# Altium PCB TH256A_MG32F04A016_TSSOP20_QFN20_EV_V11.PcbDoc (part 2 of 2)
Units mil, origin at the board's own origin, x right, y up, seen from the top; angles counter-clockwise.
Board outline 4094.49 x 2637.8 mil, 2 copper layers (Top Layer, Bottom Layer); 134 components, 99 nets, 551 pads, 259 vias.
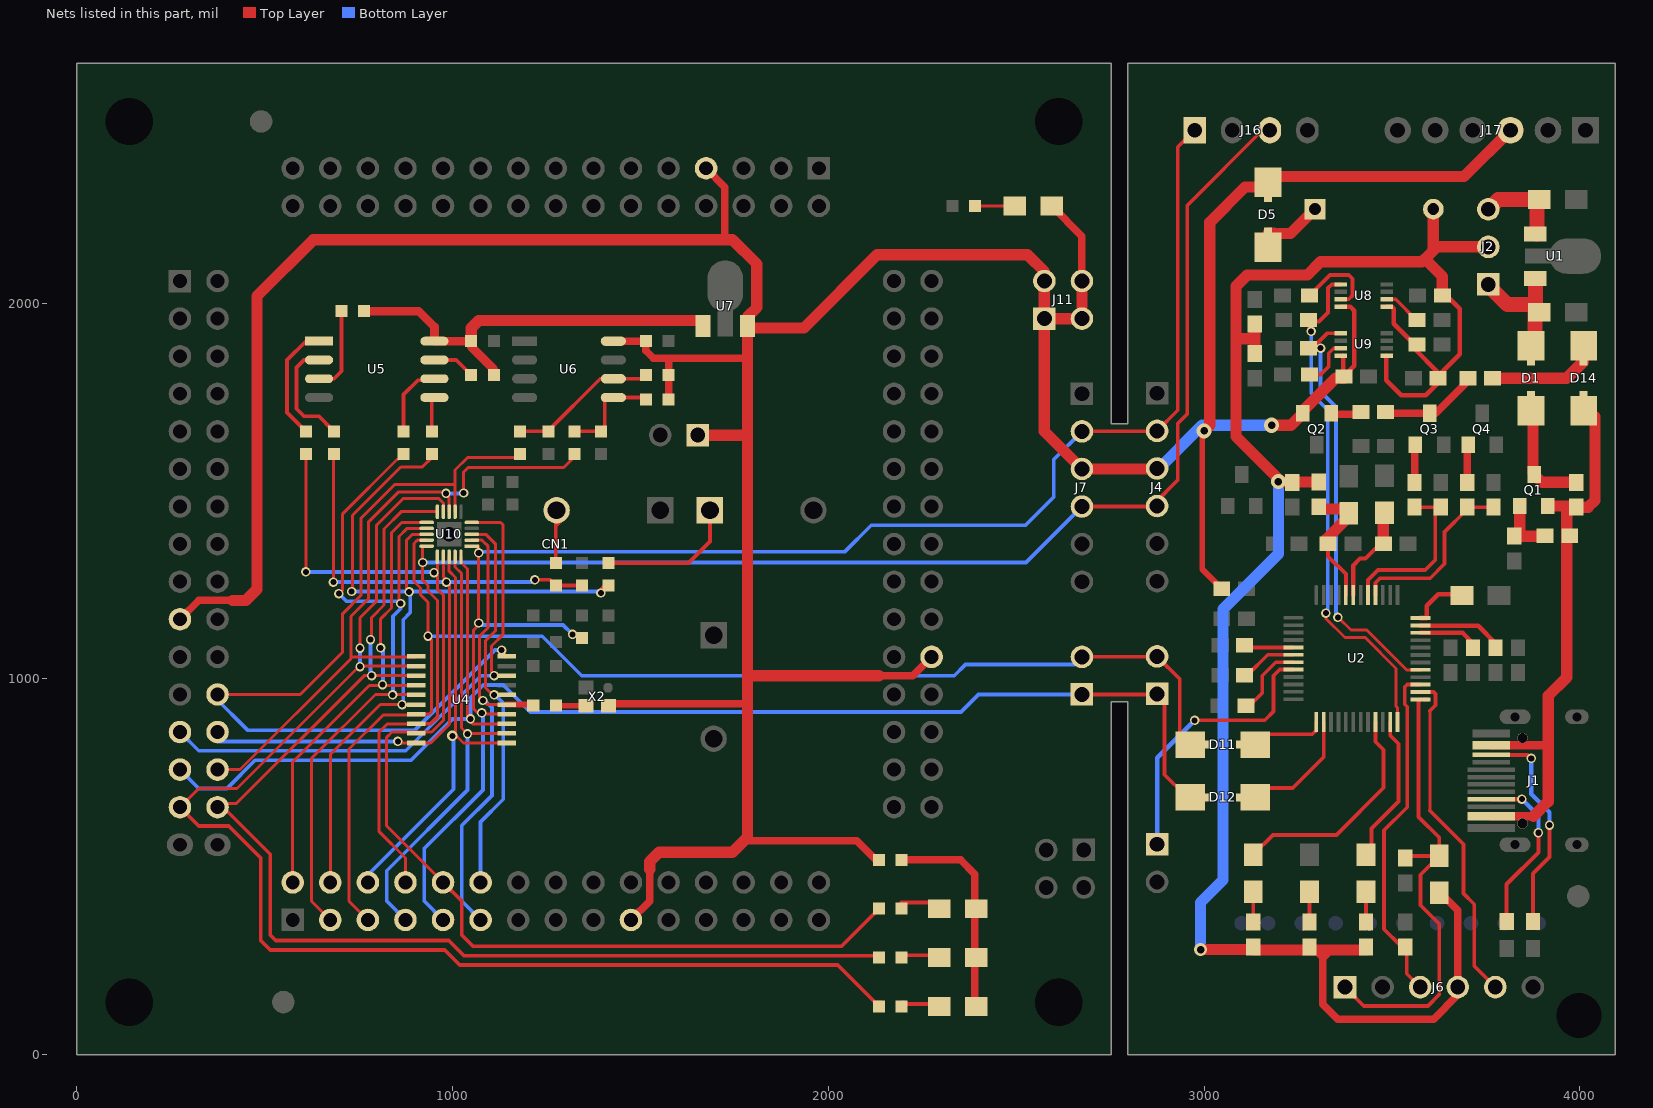
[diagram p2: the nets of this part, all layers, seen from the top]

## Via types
v1: diameter 20, hole 12, Top Layer to Bottom Layer, tented both sides, 173 vias
v2: diameter 25, hole 16, Top Layer to Bottom Layer, tented both sides, 58 vias
v3: diameter 30, hole 12, Top Layer to Bottom Layer, tented both sides, 13 vias
v4: diameter 25, hole 12, Top Layer to Bottom Layer, tented both sides, 6 vias
v5: diameter 40, hole 20, Top Layer to Bottom Layer, tented both sides, 3 vias
v6: diameter 28, hole 16, Top Layer to Bottom Layer, tented both sides, 2 vias
v7: diameter 30, hole 16, Top Layer to Bottom Layer, tented both sides, 2 vias
v8: diameter 35, hole 20, Top Layer to Bottom Layer, tented both sides, 1 vias
v9: diameter 15, hole 12, Top Layer to Bottom Layer, tented both sides, 1 vias

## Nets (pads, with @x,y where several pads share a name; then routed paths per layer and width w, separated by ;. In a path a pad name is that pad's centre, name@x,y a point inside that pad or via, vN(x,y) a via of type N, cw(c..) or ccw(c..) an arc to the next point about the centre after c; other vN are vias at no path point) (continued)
MLINK_RXD: CN1.5 D11.2 J5.2 J8.2 U4.17 U10.14 | length 3570.1
  Top Layer w8: CN1.5@775.04,358.74 725.04,408.74 725.04,813.74 815.04,903.74 903.88,903.74 922.44,903.74 U4.17@925.04,906.34 ; U4.17@903.88,906.34 U4.17@925.04,906.34 ; U10.14@931.41,1369.21 906.51,1369.21 897.72,1360.42 897.72,1259.06 915.04,1241.74 915.04,1223.74 935.04,1203.74 v2(935.04,1113.74) 944.04,1104.74 944.04,1093.74 ; 944.04,1063.74 944.04,1093.74 ; U4.17@925.04,906.34 937.64,906.34 944.04,912.74 944.04,1093.74
  Top Layer w10: J8.2@2675.04,1058.74 J5.2@2875.04,1058.74 ; J5.2@2875.04,1060 2935.04,1000 2935.04,825 D11.2@2935.04,810
  Bottom Layer w10: v2(935.04,1113.74) 1239.04,1113.74 1344.04,1008.74 2335.04,1008.74 2365.04,1038.74 2655.04,1038.74 J8.2@2675.04,1058.74
MLINK_TXD: CN1.117 D12.1 J5.1 J8.1 U4.3 U10.20 | length 3656.5
  Top Layer w8: U10.20@1022.91,1324.96 1022.91,1309.87 1040.04,1292.74 1040.04,894.74 1044.54,890.24 1054.04,880.74 U4.3@1144.04,880.74 ; J5.1@2875.04,960 J5.1@2880.81,954.23
  Top Layer w10: J8.1@2675.04,958.74 J5.1@2875.04,958.74 ; J5.1@2895.04,958 2895.04,745 D12.1@2948.43,691.61
  Bottom Layer w10: CN1.117@275.04,758.74 325.04,708.74 400.11,708.74 475.04,783.67 889.97,783.67 1000.04,893.74 v2@1044.04,893.74 ; v2(1048.04,893.74) 1048.04,949.74 1082.04,983.74 1135.04,983.74 1207.04,911.74 2353.04,911.74 2400.04,958.74 J8.1@2675.04,958.74
NetC2_2: C2.2 Q1.1 R5.2 | length 165
  Top Layer w30: R5.2@3825.04,1380 R5.2@3840.04,1380 ; Q1.1@3840.04,1460 R5.2@3840.04,1380 ; C2.2@3910.04,1380 3907,1380 R5.2@3840.04,1380
NetC6_1: C6.1 C7.2 R10.2 U2.44 | length 332.7
  Top Layer w11: C7.2@3330,1360 3330,1326 3377.23,1278.77 U2.44@3377.23,1223.13
  Top Layer w30: R10.2@3320.04,1452 3385,1452 C6.1@3385,1440.79 3385,1432 3324,1371 C7.2@3324,1366
NetC8_2: C8.2 C9.1 U2.43 | length 251
  Top Layer w11: U2.43@3396.92,1223.13 3396.92,1301.92 3415,1320 3429,1320 3465.5,1356.5 3477,1356.5 C8.2@3480.5,1356.5
  Top Layer w30: C8.2@3477,1360 C9.1@3477,1426.05
NetC11_1: C11.1 U2.36 | length 149.7
  Top Layer w12: U2.36@3575.5,1162.16 3592.2,1162.16 3592.2,1194.68 3622.9,1225.39 C11.1@3679.94,1225.39
NetD1_1: D1.1 Q1.3 R1.2 | length 276.4
  Top Layer w30: D1.1@3875,1698.39 3875,1546.98 Q1.3@3878.04,1543.94 3898.98,1523 R1.2@3990.04,1523
NetD2_1: D2.1 R6.2 | length 80.8
  Top Layer w10: R6.2@3130.59,353.26 D2.1@3130.59,434.05
NetD3_1: D3.1 R9.2 | length 80.8
  Top Layer w10: R9.2@3430.59,353.26 D3.1@3430.59,434.05
NetD4_1: D4.1 R11.2 | length 80.8
  Top Layer w10: R11.2@3280.59,353.26 D4.1@3280.59,434.05
NetD5_1: D5.1 SW1.1 | length 154.2
  Top Layer w30: D5.1@3170,2185.93 3185.93,2185.93 3185,2185 3230.04,2185 SW1.1@3295.04,2250
NetD8_1: D8.1 D9.1 D10.1 R58.1 | length 550.6
  Top Layer w20: R58.1@2195.04,518.74 2351.9,518.74 2390,480.64 2390,388.74 2390,258.74 D10.1@2390,140.79
NetD8_2: D8.2 R54.2 | length 95.8
  Top Layer w10: 2195.04,405 D8.2@2290.79,405
NetD9_2: D9.2 R55.2 | length 95.8
  Top Layer w10: R55.2@2189.94,265 2195.04,265 D9.2@2285.73,265
NetD10_2: D10.2 R56.2 | length 95.8
  Top Layer w10: R56.2@2196.58,140 R56.2@2200,140 ; R56.2@2199.94,135 D10.2@2292.3,135
NetD11_1: D11.1 U2.13 | length 188.6
  Top Layer w10: D11.1@3136.65,852.74 3288.04,852.74 3298.49,863.19 U2.13@3298.49,885.65
NetD12_2: D12.2 U2.14 | length 296
  Top Layer w10: D12.2@3150.04,709.74 3236.14,709.74 3318.18,791.78 U2.14@3318.18,885.65
NetD13_2: D13.2 R43.2 | length 105.8
  Top Layer w8: R43.2@2390.04,2258.74 D13.2@2495.83,2258.74
NetD14_2: D14.2 R17.1 | length 272.5
  Top Layer w30: R17.1@3768,1800 3965,1800 D14.2@4009.08,1844.07 ; D14.2@3998.15,1868.15 D14.2@4010,1868.15 ; D14.2@4004.08,1844.07 D14.2@4005,1845
NetJ1_A5: J1.A5 R26.1 | length 460.3
  Top Layer w11: J1.A5@3763.84,679.9 v2(3845.59,679.9) ; R26.1@3805.04,354.74 3805.04,453.74 3890.04,538.74 v2@3890.04,590.74
  Bottom Layer w11: v2(3845.59,679.9) 3889.59,635.9 v2(3889.59,590.74)
NetJ1_B5: J1.B5 R27.2 | length 582.9
  Top Layer w11: J1.B5@3763.84,798.01 3861.32,798.01 v2(3870.59,788.74) ; R27.2@3875.04,354.74 3875.04,481.74 3919.04,525.74 v2(3919.04,610.74)
  Bottom Layer w11: v2(3870.59,788.74) 3870.59,693.74 3919.04,645.29 v2(3919.04,610.74)
NetQ2_1: Q2.1 R18.2 | length 72
  Top Layer w20: Q2.1@3338,1703.94 R18.2@3410,1703.94
NetQ3_1: Q3.1 R19.2 | length 97.5
  Top Layer w20: R19.2@3560.04,1523 Q3.1@3560.04,1620.53
NetQ3_2: Q3.2 R17.2 R18.1 | length 242.2
  Top Layer w20: R18.1@3503.03,1706.97 Q3.2@3600.54,1706.97 3616.97,1706.97 3702,1792 R17.2@3702,1800
NetQ4_1: Q4.1 R23.2 | length 97.5
  Top Layer w20: R23.2@3700.04,1523 Q4.1@3700.04,1620.53
NetR15_1: R15.1 U2.35 | length 263.6
  Top Layer w12: U2.35@3575.5,1141.47 3605.04,1141.47 ; 3637.3,1141.47 3605.04,1141.47 ; R15.1@3775.59,1083 3775.59,1095 3729.12,1141.47 3605.04,1141.47
NetR16_1: R16.1 U2.34 | length 163.6
  Top Layer w12: U2.34@3575.5,1122.79 3687.8,1122.79 3715.59,1095 R16.1@3715.59,1083
NetR29_2: R29.2 U8.7 | length 202.9
  Top Layer w10: R29.2@3295,2035 3335,2075 3385,2075 3395,2065 3395,2020 3385.16,2010.16 U8.7@3363.98,2010.16 U8.7@3361.86,2010.16
NetR30_2: R30.2 U9.7 | length 132.5
  Top Layer w10: R30.2@3281,1810 3310,1810 3331.5,1831.5 3331.5,1866.5 3345.16,1880.16 U9.7@3363.98,1880.16
NetR59_1: R59.1 U5.7 | length 114.5
  Top Layer w10: U5.7@952.13,1848.74 1010.04,1848.74 R59.1@1050.04,1808.74
NetR60_2: R60.2 U5.3 | length 218.2
  Top Layer w10: U5.3@645.04,1798.74 684.91,1798.74 705.04,1818.87 R60.2@705.04,1968.74
NetR64_2: R64.2 U8.2 | length 108.2
  Top Layer w10: U8.2@3486.02,2010.16 3509.84,2010.16 R64.2@3566,1954 ; R64.2@3553.5,1968.5 R64.2@3557,1965
NetR70_1: R70.1 SW4.2 | length 169.2
  Top Layer w10: R70.1@1275.04,1308.74 1275.04,1406.54 ; SW4.2@1275.04,1446.54 1275.04,1406.54 ; SW4.2@1297.24,1428.74 1275.04,1406.54
NetR72_2: R72.2 SW3.1 | length 376.6
  Top Layer w10: R72.2@1415.04,1308.74 1628.04,1308.74 1685.04,1365.74 SW3.1@1685.04,1448.74
P44: J6.5 U2.26 | length 900.8
  Top Layer w8: 3600.59,650 3600.59,915
  Top Layer w10: U2.26@3575.5,965.31 3610.28,965.31 3615.59,960 3615.59,930 3600.59,915 ; 3600.59,650 3690.59,560 3690.59,429 3719.14,400.45 3719.14,235.9 J6.5@3775.04,180
P45: J6.3 R25.1 U2.27 | length 931.6
  Top Layer w10: R25.1@3539.32,290.72 3539.32,287 3539.32,215.72 J6.3@3575.04,180 ; R25.1@3540.59,292 3535.59,292 3521.03,292 3479.04,333.99 3479.04,597.19 3540.59,658.74 3540.59,926 3534,932.59 3534,978.41 3540.58,984.99 U2.27@3575.5,984.99 ; J6.3@3576.32,181.28 J6.3@3583.59,174
PA0: CN1.114 R61.1 U4.10 U10.7 | length 2264.6
  Top Layer w8: CN1.114@375.04,958.74 595.04,958.74 708.04,1071.74 708.04,1173.74 757.35,1223.05 757.35,1428.51 845.61,1516.77 1007.16,1516.77 ; U10.7@1007.16,1444.96 1007.16,1516.77 ; U4.10@1135.92,1059.23 U4.10@1138.04,1059.23 ; U4.10@1138.04,1058.94 U4.10@1138.04,1059.23 ; v2@1138.04,1075.74 1138.04,1059.94 U4.10@1138.04,1059.23 ; U4.10@1144.04,1059.94 1143.33,1059.23 U4.10@1138.04,1059.23 ; R61.1@1180.04,1588.74 1040.04,1588.74 1007.16,1555.86 1007.16,1516.77
  Bottom Layer w10: CN1.114@360.04,958.74 367.54,951.24 455.04,863.74 900.04,863.74 1113.04,1076.74 v2(1131.04,1076.74)
PA0_I2C1_SCL: C46.1 R61.2 R68.2 U6.6 | length 381.4
  Top Layer w10: R61.2@1180.04,1658.74 1253.41,1658.74 1254.22,1659.56 1393.41,1798.74 U6.6@1428.15,1798.74 R68.2@1503.41,1798.74
PA1: CN1.115 U4.8 U10.5 | length 1428.8
  Top Layer w8: U10.5@1051.41,1416.46 1128.39,1416.46 1135.04,1409.8 1135.04,1118.74 1104.04,1087.74 1104.04,1019.74
  Bottom Layer w10: CN1.115@275.04,858.74 325.04,808.74 876.04,808.74 1076.04,1008.74 v2(1111.04,1008.74)
PA2: CN1.116 R52.1 R70.2 R71.1 U4.20 U10.17 | length 2073.4
  Top Layer w8: v2@684.04,1261.74 R52.1@684.04,1598.74 ; v2@864.24,829.54 U4.20@903.88,829.54 942.04,829.54 992.04,879.54 v2@992.04,1255.74 ; U10.17@975.67,1324.96 975.67,1272.11 v2@987.04,1260.74
  Top Layer w10: v2(1219.45,1263.74) 1260.04,1263.74 R70.2@1275.04,1248.74 R71.1@1345.04,1248.74
  Bottom Layer w10: CN1.116@375.04,833.74 v2(855.04,833.74) v2@860.04,833.74 ; v2(683.04,1257.74) v2(984.04,1257.74) v2@1209.04,1257.74
PA2_SPI_MISO: R52.2 U5.2 | length 296
  Top Layer w10: U5.2@645.04,1848.74 605.04,1848.74 585.04,1828.74 585.04,1718.74 605.04,1698.74 644.94,1698.74 R52.2@679.94,1663.74
PA4: CN1.118 R51.1 U4.11 U10.8 | length 1739.4
  Top Layer w8: CN1.118@375.04,758.74 435.04,758.74 730.04,1053.74 730.04,1057.74 ; U4.11@903.88,1059.94 901.68,1057.74 730.04,1057.74 ; U10.8@991.41,1444.96 991.41,1482.37 981.54,1492.24 977.01,1496.77 855.61,1496.77 777.35,1418.51 777.35,1214.05 730.04,1166.74 730.04,1057.74 ; v2(1030.04,1494.74) 1030.04,1550.74 1042.04,1562.74 1296.04,1562.74 R51.1@1324.54,1591.24
  Bottom Layer w10: v2(983.04,1493.74) v2@1029.04,1493.74
PA4_I2C1_SDA: C45.1 R51.2 R57.2 U6.5 | length 245.9
  Top Layer w10: R51.2@1325.04,1658.74 C45.1@1395.04,1658.74 ; C45.1@1405.04,1658.74 1405.04,1748.74 U6.5@1405.04,1752.74 ; U6.5@1428.15,1748.74 R57.2@1510.04,1748.74
PA5: CN1.119 R56.1 U4.12 U10.9 | length 3625.2
  Top Layer w8: CN1.119@275.04,658.74 325.04,708.74 427.04,708.74 748.54,1030.24 748.54,1032.74 748.54,1035.24 v2@749.04,1035.74 ; v2@749.04,1034.34 754.04,1034.34 U4.12@903.88,1034.34 ; v2@749.04,1081.74 751.54,1084.24 754.04,1086.74 754.04,1162.74 797.97,1206.67 797.97,1409.14 868.52,1479.69 964.09,1479.69 975.67,1468.11 U10.9@975.67,1444.96
  Top Layer w10: CN1.119@275.04,658.74 325.04,608.74 405.04,608.74 490.04,523.74 490.04,303.74 515.04,278.74 979.68,278.74 1019.68,238.74 2025.04,238.74 2123.78,140 2135.04,140 R56.1@2140,140
  Bottom Layer w10: v2@754.04,1035.74 v2(754.04,1081.74)
  other v2: 754.04,1032.74
PA6: CN1.120 R55.1 U4.13 U10.10 | length 3259.2
  Top Layer w8: CN1.120@375.04,658.74 390.04,658.74 400.04,668.74 425.04,668.74 765.04,1008.74 v2(785.04,1008.74) U4.13@903.88,1008.74 ; v2@785.04,1104.74 785.04,1163.74 817.97,1196.67 817.97,1399.14 863.8,1444.96 U10.10@959.92,1444.96
  Top Layer w10: CN1.120@390.04,658.74 515.04,533.74 515.04,318.74 530.04,303.74 990.04,303.74 1030.04,263.74 2118.74,263.74
  Bottom Layer w10: v2@782.04,1008.74 v2(782.04,1104.74) ; v2@783.54,1106.24 v2@785.04,1104.74
PA7: CN1.2 U4.14 U10.11 | length 1287.9
  Top Layer w8: CN1.2@575.04,458.74 575.04,508.74 ; 575.04,538.74 575.04,508.74 ; v2(809.04,1082.74) 809.04,1159.81 837.97,1188.74 837.97,1389.14 865.29,1416.46 U10.11@931.41,1416.46 ; U4.14@903.88,983.14 814.04,983.14 813.95,983.14 813.2,983.9 811.2,985.9 808.04,982.74 779.04,982.74 575.04,778.74 575.04,508.74
  Bottom Layer w10: v2@815.04,983.74 815.04,984.74 v2@815.04,1082.74
  other v2: 814.04,984.74
PA8: CN1.3 R65.1 U4.15 U10.12 | length 1929.2
  Top Layer w8: CN1.3@675.04,358.74 625.04,408.74 625.04,788.74 795.04,958.74 841.04,958.74 903.88,958.74 U4.15@905.04,958.74 ; v2(698.04,1226.74) 708.04,1236.74 708.04,1439.2 852.58,1583.74 855.04,1583.74 R65.1@870.04,1598.74 ; v2@857.97,1205.74 857.97,1379.14 879.54,1400.71 U10.12@931.41,1400.71
  Bottom Layer w10: v2(698.04,1226.74) 718.04,1206.74 v2@862.04,1206.74 ; v2@842.04,958.74 842.04,1166.74 862.04,1186.74 v2(862.04,1200.74) v2@862.04,1205.74
  other v2: 841.04,957.74
PA8_SPI_SCK: R65.2 U5.6 | length 217.2
  Top Layer w10: R65.2@870.04,1658.74 870.04,1756.52 908.52,1795 952.13,1795 U5.6@973.54,1795
PA9: CN1.4 R53.1 R72.1 U4.16 U10.13 | length 2287.5
  Top Layer w8: CN1.4@675.04,458.74 675.04,798.74 808.24,931.94 866.04,931.94 U4.16@903.88,931.94 ; v2@734.35,1232.74 734.35,1435.51 862.58,1563.74 920.04,1563.74 945.04,1588.74 R53.1@945.04,1598.74 ; v2@877.35,1240.43 877.35,1368.51 893.8,1384.96 U10.13@931.41,1384.96
  Top Layer w10: v2(1395.04,1228.74) 1395.04,1238.74 R72.1@1410.04,1253.74
  Bottom Layer w10: v2@734.35,1232.74 885.04,1232.74 v2@1395.04,1232.74 ; v2@869.04,940.94 869.04,1157.74 888.04,1176.74 v2@888.04,1228.74
  other v2: 866.04,931.74 885.04,1231.74 732.04,1232.74
PA9_SPI_MOSI: R53.2 U5.5 | length 90
  Top Layer w10: R53.2@945.04,1658.74 U5.5@945.04,1748.74
PA11: CN1.6 U4.1 U10.18 | length 1107.6
  Top Layer w8: U10.18@991.41,1324.96 991.41,1286.37 1008.04,1269.74 1008.04,850.74 1029.24,829.54 U4.1@1144.04,829.54
  Bottom Layer w10: CN1.6@775.04,458.74 775.04,478.74 1002.54,706.24 v6@1002.54,846.24
  other v6: 1000.04,848.74
PA12: CN1.7 U4.2 U10.19 | length 1193
  Top Layer w8: U10.19@1007.16,1324.96 1007.16,1297.74 1024.04,1280.86 1024.04,869.74 1038.64,855.14 1040.04,855.14 U4.2@1144.04,855.14
  Bottom Layer w10: CN1.7@875.04,358.74 825.04,408.74 825.04,489.66 1040.04,704.66 v2(1040.04,853.74)
PA13_SWDIO: CN1.8 J4.4 J7.4 J16.3 U4.18 U10.15 | length 4405.8
  Top Layer w8: CN1.8@875.04,458.74 875.04,523.74 805.04,593.74 805.04,858.74 827.04,880.74 U4.18@903.88,880.74 ; U10.15@920.04,1353.74 920.04,1353.46 920.04,1309.74 920.04,1263.74 935.04,1248.74 935.04,1233.74 960.04,1208.74 960.04,898.74
  Top Layer w10: U4.18@903.88,880.74 942.04,880.74 960.04,898.74 ; J7.4@2675.04,1458.74 J4.4@2860.04,1458.74 ; J4.4@2868.04,1467 2930.04,1529 2930.04,1680 2955.04,1705 2955.04,2260.04 3155,2460 J16.3@3175.04,2460
  Bottom Layer w10: v2@920.04,1309.74 v2(921.04,1309.74) 1680.04,1309.74 ; 1880.04,1309.74 1680.04,1309.74 ; J7.4@2675.04,1458.74 2526.04,1309.74 1680.04,1309.74
PA14_SWCLK: CN1.9 J4.2 J7.2 J16.1 R69.1 U4.4 U10.1 | length 4290.9
  Top Layer w8: U10.1@1070.04,1353.74 1070.04,1353.46 v2(1070.04,1335.74) v2(1070.04,1148.74) 1070.04,1143.74 1056.04,1129.74 1056.04,920.74 v2@1070.44,906.34 ; v2@1078.04,906.34 U4.4@1144.04,906.34
  Top Layer w10: v2@1315.04,1113.74 1319.45,1113.74 R69.1@1345.04,1113.74 ; J7.2@2675.04,1658.74 J4.2@2875.04,1658.74 ; J4.2@2875.04,1660 2930.04,1715 2930.04,2415 J16.1@2975.04,2460
  Bottom Layer w10: CN1.9@975.04,358.74 925.04,408.74 925.04,548.74 1081.04,704.74 v2@1081.04,909.74 ; v2@1070.04,1143.74 1294.45,1143.74 v2(1319.45,1118.74) ; v2@1070.04,1333.74 1071.04,1334.74 1075.04,1338.74 2044.68,1338.74 2114.68,1408.74 2525.04,1408.74 2600.04,1483.74 2600.04,1583.74 J7.2@2675.04,1658.74
  other v2: 1078.04,909.74
PA15: CN1.10 R54.1 R66.1 U4.19 U10.16 | length 3029.1
  Top Layer w8: v2@610.04,1294.74 R66.1@610.04,1598.74 ; U10.16@959.92,1324.96 959.92,1282.74 959.92,1238.86 976.04,1222.74 976.04,889.94 944.84,858.74 903.88,858.74 839.04,858.74 825.04,844.74 825.04,608.74 CN1.10@975.04,458.74
  Top Layer w10: CN1.10@975.04,458.74 1025.04,408.74 1025.04,318.74 1055.04,288.74 2035.04,288.74 R54.1@2135.04,388.74
  Bottom Layer w10: v2(610.04,1284.74) v2@951.04,1284.74
  other v2: 951.04,1282.74
PA15_SPI_NSS: R66.2 U5.1 | length 316.4
  Top Layer w10: R66.2@610.04,1658.74 560.04,1708.74 560.04,1848.74 610.04,1898.74 U5.1@645.04,1898.74
PASS: D3.2 U2.23 | length 394.2
  Top Layer w10: D3.2@3445.59,530 3445.59,532.47 3445.59,602.29 3517.04,673.74 3517.04,827.74 3495.34,849.44 U2.23@3495.34,885.65
PB0: CN1.11 R67.1 U4.5 U10.2 | length 1262.9
  Top Layer w8: U10.2@1051.41,1369.21 1078.57,1369.21 1095.04,1352.74 1095.04,1136.74 1072.04,1113.74 1072.04,951.74 v2(1081.04,942.74) 1091.84,931.94 U4.5@1144.04,931.94
  Top Layer w15: U4.5@1144.04,931.94 R67.1@1215.04,931.94
  Bottom Layer w10: CN1.11@1075.04,358.74 1025.04,408.74 1025.04,609.66 1105.04,689.66 1105.04,923.74 1086.04,942.74 v2(1081.04,942.74)
PB0_OSCIN: R67.2 X2.3 | length 80
  Top Layer w15: R67.2@1275.04,928.74 X2.3@1355.04,928.74
PB1: CN1.12 U4.6 U10.3 | length 1065.9
  Top Layer w8: U10.3@1051.41,1384.96 1088.82,1384.96 1115.04,1358.74 1115.04,1128.74 1088.04,1101.74 1088.04,976.74 1107.24,957.54 v2(1111.04,957.54) U4.6@1144.04,957.54
  Bottom Layer w10: CN1.12@1075.04,458.74 1075.04,619.74 1135.04,679.74 1135.04,935.74 v2@1112.14,958.64
RST: C12.2 J6.1 R22.2 U2.25 | length 1228.1
  Top Layer w10: J6.1@3375.04,180 3425.04,130 3595.59,130 3625.59,160 3625.59,348 3575.59,398 3575.59,479.21 C12.2@3625.59,529.21 ; R22.2@3541.8,529.21 C12.2@3625.59,529.21 ; U2.25@3575.59,945 3570.59,940 3570.59,633 3625.59,578 C12.2@3625.59,529.21 ; U2.25@3585.04,945.62 U2.25@3594.42,945.62
RST_CTRL_51: R19.1 R20.1 U2.41 | length 451.6
  Top Layer w10: U2.41@3436.29,1223.13 3436.29,1263.29 3463,1290 3588.74,1290 3615.04,1316.3 R20.1@3615.04,1457 ; R19.1@3560.04,1457 R20.1@3615.04,1457 ; R20.1@3630.04,1457 R20.1@3615.04,1457
RST_CTRL_ARM: R23.1 R24.1 U2.40 | length 474.1
  Top Layer w10: U2.40@3455.97,1223.13 3455.97,1256.14 3467.84,1268 3601.74,1268 3640.04,1306.3 3640.04,1391.3 R23.1@3697.5,1448.76 ; R23.1@3700.04,1457 R24.1@3770.04,1457
SWD_SCL_DIR: R63.2 U2.29 U9.5 | length 1149.4
  Top Layer w8: v2@3356.5,1164.5 3391,1130 3433,1130 3538.64,1024.36 U2.29@3575.5,1024.36
  Top Layer w10: R63.2@3289,1869 R63.2@3295,1875 ; R63.2@3290,1883 R63.2@3290.22,1882.64 ; R63.2@3292.47,1879.04 R63.2@3290.22,1882.64 ; R63.2@3292.93,1875 R63.2@3295,1875 ; v2@3311.93,1875 3310,1875 R63.2@3295,1875 ; U9.5@3363.98,1919.53 3327.11,1919.53 3298.79,1891.21 R63.2@3290.22,1882.64
  Bottom Layer w10: v2(3310,1880) 3310,1764.49 3351,1723.49 3351,1495 ; 3351,1505 3351,1495 ; v2@3361,1160 3356.5,1164.5 3351,1170 3351,1495
  other v2: 3356,1164
SWD_SDA_DIR: R62.2 U2.24 U8.5 | length 1381.2
  Top Layer w8: v2(3324,1175) 3324,1161 3375,1110 3429,1110 3511,1028 3511,927 3515.03,922.97 U2.24@3515.03,885.65
  Top Layer w10: v2@3280,1925 R62.2@3280,1951 ; R62.2@3282,1951 R62.2@3285,1951 ; R62.2@3285,1957 3285,1955 R62.2@3285,1951 ; U8.5@3363.98,2049.53 3339.53,2049.53 3330,2040 3330,1975 3306,1951 R62.2@3285,1951
  Bottom Layer w10: v2(3285,1925) 3285,1760 3329,1716 3329,1485 ; v2@3329,1175 3329,1485 ; 3329,1505 3329,1485
TOOL_OPTION0: R2.1 U2.5 | length 121.1
  Top Layer w10: R2.1@3118.04,1080 3121.96,1083.92 U2.5@3237.52,1083.92
TOOL_OPTION1: R3.1 U2.6 | length 142.8
  Top Layer w10: R3.1@3116.54,1011.54 3169.23,1064.23 U2.6@3237.52,1064.23
TOOL_OPTION2: R28.1 U2.7 | length 191.4
  Top Layer w10: R28.1@3121.04,928.74 3155.04,962.74 3155.04,1008.74 3190.85,1044.55 U2.7@3237.52,1044.55
USBOK: D2.2 U2.21 | length 605
  Top Layer w10: D2.2@3130.59,532.47 3183.12,585 3352.3,585 3477.67,710.37 3477.67,811.43 3455.97,833.13 U2.21@3455.97,885.65
VCC3: C47.1 R59.2 R60.1 U5.8 U7.1 | length 1115.4
  Top Layer w23: R60.1@765.04,1978.74 910.04,1978.74 952.13,1936.65 U5.8@952.13,1898.74 C47.1@1050.04,1898.74 1050.04,1883.74 1110.04,1823.74 R59.2@1110.04,1808.74
  Top Layer w30: C47.1@1050.04,1898.74 1050.04,1933.74 1070.04,1953.74 U7.1@1666.93,1953.74
VCC_USB: C2.1 D14.1 J1.A4 J1.A9 J1.M5 J1.M6 Q1.2 R1.1 | length 1456.2
  Top Layer w22: J1.A4@3763.84,634.61 3847.24,634.61 3876.67,634.61 ; J1.A9@3763.84,823.62 3847.24,823.62 3915.59,823.62
  Top Layer w30: 3876.67,634.61 3915.59,673.54 3915.59,823.62 3915.59,955 3964.92,1004.33 3964.92,1381.26 3964.92,1446.88 ; Q1.2@3915.04,1460 3967.04,1460 ; R1.1@3980.04,1457 R1.1@3990.04,1457 4022,1457 4040,1475 D14.1@4040,1698.39
VCP_OPTION: J3.1 U2.8 | length 845.4
  Top Layer w10: v2(2975,890) 3000.04,890 ; 3100.04,890 3000.04,890 ; U2.8@3237.52,1024.86 3201.16,1024.86 3185.04,1008.74 3185.04,913.74 3161.3,890 3000.04,890
  Bottom Layer w12: J3.1@2875.04,560 2875.04,790.04 v2(2975,890)
VDD: C12.1 J2.2 J6.4 R4.1 R6.1 R9.1 R10.1 R11.1 R12.1 R13.1 R14.2 R40.2 R41.2 SW1.2 U8.1 U9.1 | length 5168.8
  Top Layer w12: R11.1@3289.78,279.52 3290.3,279 3315.59,253.71 3315.94,253.36 ; 3315.95,251.65 3342.11,277.81 ; U9.1@3485,1860.47 3485,1795 3525,1755 3590,1755 3623,1788 R40.2@3623,1800 ; U8.1@3486.02,1990.47 3499.53,1990.47 3505,1985 3505,1945 ; 3505,1955 3505,1945 ; R40.2@3623,1798 R40.2@3623,1800 ; R40.2@3623,1805 R40.2@3623,1800 ; R40.2@3623,1815 3557.5,1880.5 3557,1881 3557,1890 3557,1893 3505,1945 ; R4.1@3640,2025 3680,1985 3680,1863.83 3623,1806.83 R40.2@3623,1800
  Top Layer w20: 3315.59,279 3315.59,253.71 3315.59,135 3355.59,95 3610.59,95 3675.04,159.45 J6.4@3675.04,180 3675.04,384.55 3635.59,424 C12.1@3635.59,430.79
  Top Layer w30: v8(2990.59,280) R6.1@3130.59,280 ; 3085,1645 3192.99,1537.01 v5@3192.99,1525 ; 3085,1645.64 3085,1905 ; R6.1@3130.59,279 3280.59,279 3290.3,279 3315.59,279 R9.1@3430.59,279 ; R12.1@3135,1866 3135,1905 ; R13.1@3135,1944 3135,1905 ; v5@3207.25,1524.26 3235,1524.26 R10.1@3305,1524.26 ; 3610,2150 SW1.2@3610,2250 ; R4.1@3634,2020 3634,2071 3587.5,2117.5 ; J2.2@3756.42,2150 3620,2150 3587.5,2117.5 ; 3085,1905 3135,1905 ; 3085,1905 3085,2045 3115,2075 3275,2075 3310,2110 3580,2110 3587.5,2117.5
  Bottom Layer w30: v8(2990.59,280) 2990.59,405 3050.59,465 3050.59,1185.55 3197.99,1332.95 v5(3197.99,1525)
VDD3: C5.1 J2.3 U1.1 | length 238.5
  Top Layer w40: J2.3@3756.42,2249.69 3782.68,2275.94 C5.1@3886.38,2275.94 ; U1.1@3886.38,2184.06 C5.1@3886.38,2275.94 ; C5.1@3892.17,2275.94 C5.1@3886.38,2275.94
VDD5: C4.1 D1.2 J2.1 U1.3 | length 287.7
  Top Layer w40: J2.1@3754.94,2048.21 3807.2,1995.94 3881.38,1995.94 U1.3@3881.38,2065.94 ; D1.2@3880,1901.61 C4.1@3880,1971.26
VDUT: C17.1 C44.1 CN1.19 CN1.39 CN1.67 CN1.109 D5.2 D13.1 J4.3 J7.3 J11.1 J11.2 J11.3 J11.4 J17.3 JP3.1 Q2.2 R7.1 R57.1 R58.2 R68.1 U6.8 U7.3 U8.8 U9.8 X2.4 | length 11361.2
  Top Layer w12: U8.8@3363.98,1990.47 3389.53,1990.47 3400,1980 3400,1833 C17.1@3372,1805 ; U9.8@3370,1860.47 3370,1805 C17.1@3371,1804
  Top Layer w15: v5@2995,1660.64 2995,1660 2995,1292 R7.1@3047,1240
  Top Layer w20: CN1.109@275.04,1158.74 325.04,1208.74 415.04,1208.74 ; X2.4@1415.04,933.74 1785.04,933.74 ; U6.8@1428.15,1898.74 C44.1@1515.04,1898.74 1515.04,1873.74 1535.04,1853.74 1785.04,1853.74 ; CN1.19@1475.04,358.74 1525.04,408.74 1525.04,493.74 ; R57.1@1575.04,1743.74 R68.1@1575.04,1808.74 1575.04,1853.74 ; CN1.67@1675.04,2358.74 1725.04,2308.74 1725.04,2168.74 ; 1786.3,570 2075.64,570 R58.2@2130.97,514.67 ; 2135.04,1008.74 2225.04,1008.74 CN1.39@2275.04,1058.74 ; D13.1@2594.25,2258.74 2675.04,2177.95 J11.4@2675.04,2058.74
  Top Layer w30: 415.04,1208.74 450.04,1208.74 480.04,1238.74 480.04,2018.74 630.04,2168.74 1725.04,2168.74 1745.04,2168.74 1810.04,2103.74 1810.04,1988.74 1785.04,1963.74 U7.3@1785.04,1948.74 ; 1525.04,493.74 1525.04,513.74 1550.04,538.74 1745.04,538.74 1785.04,578.74 1785.04,933.74 1785.04,1008.74 ; 1685.04,1648.74 1785.04,1648.74 ; 2135.04,1008.74 1785.04,1008.74 ; J11.4@2675.04,2058.74 J11.3@2675.04,1958.74 J11.1@2575.04,1958.74 ; J4.3@2875.04,1558.74 J7.3@2675.04,1558.74 2575.04,1658.74 J11.1@2575.04,1958.74 ; v5@2999.97,1660.03 3015,1675.06 3015,2215 3109.06,2309.06 3169.09,2309.06 3175.83,2315.79 3196.65,2336.61 3691.65,2336.61 J17.3@3815.04,2460 ; v5(3180,1675) 3231.03,1675 Q2.2@3263,1706.97 ; Q2.2@3259.98,1709.98 C17.1@3350,1800 ; C17.1@3365,1800 C17.1@3372,1800 ; 1785.04,1008.74 1785.04,1648.74 ; 1785.04,1648.74 1785.04,1853.74 U7.3@1785.04,1938.74 U7.3@1785.04,1948.74 ; U7.3@1785.04,1948.74 1790.04,1943.74 1800.04,1933.74 1935.04,1933.74 2130.04,2128.74 2530.04,2128.74 2575.04,2083.74 J11.2@2575.04,2058.74 J11.1@2575.04,1958.74
  Bottom Layer w30: J4.3@2876.89,1556.89 2877.52,1557.52 2990,1670 2995,1675 3000,1675 v5(3180,1675)
  other v5: 3000,1660
pads on no net: CN1.1 CN1.13 CN1.14 CN1.15 CN1.16 CN1.18 CN1.20 CN1.21 CN1.22 CN1.23 CN1.24 CN1.25 CN1.26 CN1.27 CN1.28 CN1.29 CN1.30 CN1.31 CN1.32 CN1.33 CN1.34 CN1.35 CN1.36 CN1.37 CN1.38 CN1.40 CN1.42 CN1.43 CN1.44 CN1.45 CN1.46 CN1.47 CN1.48 CN1.49 CN1.50 CN1.51 CN1.52 CN1.53 CN1.54 CN1.55 CN1.56 CN1.57 CN1.58 CN1.59 CN1.60 CN1.61 CN1.62 CN1.63 CN1.64 CN1.65 CN1.66 CN1.68 CN1.70 CN1.71 CN1.72 CN1.73 CN1.74 CN1.75 CN1.76 CN1.77 CN1.78 CN1.79 CN1.80 CN1.81 CN1.82 CN1.83 CN1.84 CN1.85 CN1.86 CN1.87 CN1.88 CN1.89 CN1.90 CN1.91 CN1.92 CN1.93 CN1.94 CN1.95 CN1.96 CN1.97 CN1.98 CN1.99 CN1.100 CN1.101 CN1.102 CN1.103 CN1.104 CN1.105 CN1.106 CN1.108 CN1.110 CN1.111 CN1.112 CN1.113 CN1.121 CN1.122 J1.A8 J1.B8 J6.6 J7.1 U2.1 U2.2 U2.3 U2.4 U2.28 U2.30 U2.32 U2.37 U2.38 U2.39 U2.46 U8.3 U8.6 U9.3 U9.6 U10.0 X2.1

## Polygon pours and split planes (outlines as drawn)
GND_POWER on Top Layer "Top Layer-No Net" (hatched 90Degree grid 10 track 10, remove dead copper, pour order 1001): 25,20 4070,20 4070,2593.74 25,2593.74
GND_POWER on Bottom Layer "Top Layer-No Net" (hatched 90Degree grid 10 track 10, remove dead copper, pour order 1001): 25,20 4070,20 4070,2593.74 25,2593.74

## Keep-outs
Top Layer:
  circle w5: c550,140 r59.06
  circle w5: c491,2483.43 r59.06
  circle w5: c3995.59,421.9 r59.06
Keep-Out Layer:
  circle w7.88: c140,140 r133.86
  circle w7.88: c2613.39,140 r133.86
  circle w7.88: c2613.39,2483.43 r133.86
  circle w7.88: c140,2483.43 r133.86
  lines w15: 2796.69,938.74 2753.39,938.74 2753.39,0 0,0 0,2637.8 2753.39,2637.8 2753.39,1678.74 2796.69,1678.74 ; 4094.49,1.26 4094.49,2639.06 4094.49,1.26

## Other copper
Top Layer:
  rectangle net GND_POWER: 1059.94,1513.74 1189.94,1541.84
  pour cut-out: 2710,2623.74 2830,2623.74 2830,0 2710,0
Bottom Layer:
  pour cut-out: 2710,2625 2830,2625 2830,0 2710,0

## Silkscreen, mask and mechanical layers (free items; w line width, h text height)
Top Overlay:
  circle w10: c140,2483.43 r137.8
  circle w10: c2613.39,2483.43 r137.8
  circle w4: c2613.39,140 r137.8
  circle w10: c140,140 r137.8
  region: 2520.95,947.11 2567.86,921.46 2565.95,937.11 2615.95,937.11 2615.95,957.11 2565.95,957.11 2567.86,971.46
  region: 2614.4,1059.29 2567.5,1084.94 2569.4,1069.29 2519.4,1069.29 2519.4,1049.29 2569.4,1049.29 2567.5,1034.94
  region: 2877.11,264.05 2902.77,335.95 2887.11,334.05 2887.11,394.05 2867.11,394.05 2867.11,334.05 2852.77,335.95
  region: 2930.99,955.86 2977.89,930.21 2975.99,945.86 3005.04,945.86 3005.04,965.86 2975.99,965.86 2977.89,980.21
  region: 3004.44,1068.04 2957.54,1093.69 2959.44,1078.04 2930.04,1078.04 2930.04,1058.04 2959.44,1058.04 2957.54,1043.69
  text "When J16 Open" at 2820,2580 h45
  text "SW1 must be off" at 2820,2520.64 h45
  text "GND" at 1595.04,2423.74 h50 r90
  text "VDUT" at 1695.04,2423.74 h50 r90
  text "RST" at 3419.94,2415 h37 r90
  text "GND" at 3469.94,2415 h37 r90
  text "Power" at 3385,2350 h45
  text "Off" at 3250.9,2348.32 h45
  text "On" at 3605,2345 h45
  text "SCL" at 3930,2325 h35 r90
  text "CLK" at 4035,2325 h35 r90
  text "SDA" at 3739.94,2320 h37 r90
  text "VCC" at 3830,2320 h37 r90
  text "VDD3" at 3695,2195 h37 r90
  text "Power" at 2450.04,2158.74 h50
  text "VDD" at 3605,2115 h37
  text "VDD5" at 3575,2060 h37
  text "VDUT" at 2515.04,1840.64 h50
  text "SCL" at 2530.04,1643.74 h33
  text "VDUT" at 2495.04,1538.74 h33
  text "SDA" at 2525.04,1443.74 h33
  text "GND" at 2525.04,1338.74 h33
  text "Key1" at 1455.04,1308.74 h50
  text "Key2" at 1785.04,1293.74 h50
  text "RST" at 2530.04,1238.74 h33
  text "GND" at 85.04,1228.74 h50
  text "GND" at 2340.04,1138.74 h50
  text "PA10_TX" at 2490,1135 h38
  text "VDUT" at 45,1130.64 h50
  text "VDUT" at 2340.04,1033.74 h50
  text "RESET" at 1800.04,1008.74 h50
  text "PA0" at 439.94,933.74 h50
  text "PA3_RX" at 2500,850 h38
  text "PA2" at 440.04,830.64 h50
  text "PA1" at 95.04,828.74 h50
  text "PA4" at 440.04,730.64 h50
  text "PA3" at 75.04,728.74 h50
  text "2024.12" at 1769.94,673.74 h35
  text "PA6" at 440.04,630.64 h50
  text "TH256A_MG32F04A016" at 1304.84,601.84 h50
  text "PA7" at 485,530 h50
  text "TSSOP20_QFN20_EV_V11" at 1304.84,526.84 h45
  text "PA9" at 695.04,523.74 h50 r90
  text "PA11" at 795.04,523.74 h50 r90
  text "PA13" at 895.04,523.74 h50 r90
  text "PA15" at 995.04,523.74 h50 r90
  text "PB1" at 1100.04,523.74 h50 r90
  text "GND" at 2545,320 h50
  text "J3" at 2835.04,201.9 h45
  text "PB0" at 1100.04,168.74 h50 r90
  text "GND" at 1405.04,168.74 h50 r90
  text "PA8" at 695.04,163.74 h50 r90
  text "Open Disable VCP." at 2815.59,130 h40
  text "Open Disable VCP." at 2815.59,130 h40
  text "VDUT" at 1500.04,124.45 h50 r90
  text "PA10" at 795.04,123.74 h50 r90
  text "PA12" at 900,120 h50 r90
  text "PA14" at 1005,120 h50 r90
  text "Short Enable VCP." at 2815.59,35 h40
  text "Short Enable VCP." at 2815.59,35 h40
Mechanical 1:
  circle w7.88: c2775.04,1008.74 r33
  circle w7.88: c2775.04,1298.74 r25
  circle w7.88: c2775.04,1416.74 r25
  circle w7.88: c2775.04,1503.74 r27
  circle w7.88: c2775.04,1613.74 r27
  lines w7.88: 2753.39,1078.74 2796.69,1078.74 2796.69,1232.74 2753.39,1232.74 2753.39,1078.74
  lines w8.88: 4094.49,0 2796.69,0 2796.69,938.74 2753.39,938.74 2753.39,0 0,0 0,2637.8 2753.39,2637.8 2753.39,1678.74 2796.69,1678.74 2796.69,2637.8 4094.49,2637.8 ; 4094.49,0 4094.49,2637.8 ; 4094.49,0 4094.49,2637.8
Mechanical 2:
  lines w6: 2775.04,1031.74 2775.04,1008.74 2798.04,1008.74 ; 2775.04,1321.74 2775.04,1298.74 2798.04,1298.74 ; 2775.04,1441.74 2775.04,1418.74 2798.04,1418.74 ; 2775.04,1526.74 2775.04,1503.74 2798.04,1503.74 ; 2775.04,1636.74 2775.04,1613.74 2798.04,1613.74

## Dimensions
0,0 to 4094.49,0 on Top Overlay
0,0 to 0,2637.8 on Top Overlay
